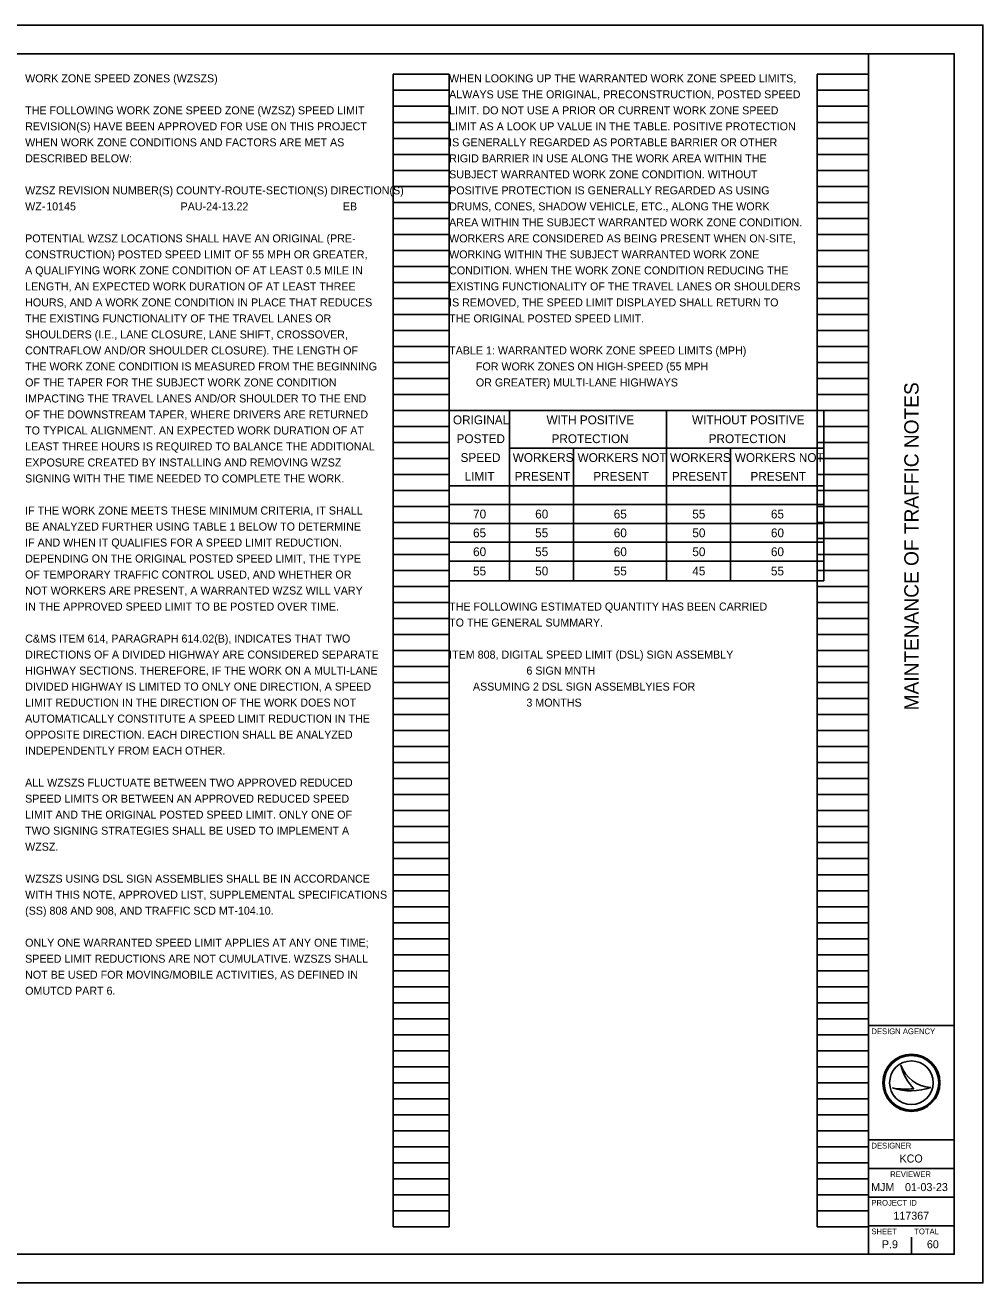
# Model space of a CAD drawing. Extents: x 0 to 34, y 0 to 22.
# Drawn here: x 17.24 to 34, y 0 to 22 of the extents above; entities that cross this region are included whole.
import ezdxf

# ---------------------------------------------------------------- set-up
doc = ezdxf.new("R2010")
doc.units = 0
for name, color, linetype in [('SH_Border', 7, 'Continuous'), ('SH_Cut_Line', 7, 'Continuous'), ('SH_Data', 7, 'Continuous'), ('SH_Text', 7, 'Continuous')]:
    doc.layers.add(name, color=color, linetype=linetype)

msp = doc.modelspace()

# ---------------------------------------------------------------- linework, layer by layer
at = {"layer": 'SH_Border'}
for p, q in [((32, 0.5), (32, 21.5)), ((32, 4.5), (33.5, 4.5)), ((32, 2.5), (33.5, 2.5)), ((32, 2), (33.5, 2)), ((32, 1.5), (33.5, 1.5)), ((32, 1), (33.5, 1))]:
    msp.add_line(p, q, dxfattribs=at)
msp.add_lwpolyline([(1.5, 21.5), (33.5, 21.5), (33.5, 0.5), (1.5, 0.5)], close=True, dxfattribs=at)
at = {"layer": 'SH_Cut_Line'}
msp.add_lwpolyline([(0, 0), (34, 0), (34, 22), (0, 22)], close=True, dxfattribs=at)
at = {"layer": 'SH_Data'}
for p, q in [((23.68, 0.98), (23.68, 21.14)), ((23.68, 21.14), (24.66, 21.14)), ((24.66, 0.98), (24.66, 21.14)), ((31.1, 0.98), (31.1, 21.14)), ((31.1, 21.14), (32, 21.14)), ((32, 0.98), (32, 21.14)), ((23.68, 20.86), (24.66, 20.86)), ((31.1, 20.86), (32, 20.86)), ((23.68, 20.58), (24.66, 20.58)), ((31.1, 20.58), (32, 20.58)), ((23.68, 20.3), (24.66, 20.3)), ((31.1, 20.3), (32, 20.3)), ((23.68, 20.02), (24.66, 20.02)), ((31.1, 20.02), (32, 20.02)), ((23.68, 19.74), (24.66, 19.74)), ((31.1, 19.74), (32, 19.74)), ((23.68, 19.46), (24.66, 19.46)), ((31.1, 19.46), (32, 19.46)), ((23.68, 19.18), (24.66, 19.18)), ((31.1, 19.18), (32, 19.18)), ((23.68, 18.9), (24.66, 18.9)), ((31.1, 18.9), (32, 18.9)), ((23.68, 18.62), (24.66, 18.62)), ((31.1, 18.62), (32, 18.62)), ((23.68, 18.34), (24.66, 18.34)), ((31.1, 18.34), (32, 18.34)), ((23.68, 18.06), (24.66, 18.06)), ((31.1, 18.06), (32, 18.06)), ((23.68, 17.78), (24.66, 17.78)), ((31.1, 17.78), (32, 17.78)), ((23.68, 17.5), (24.66, 17.5)), ((31.1, 17.5), (32, 17.5)), ((23.68, 17.22), (24.66, 17.22)), ((31.1, 17.22), (32, 17.22)), ((23.68, 16.94), (24.66, 16.94)), ((31.1, 16.94), (32, 16.94)), ((23.68, 16.66), (24.66, 16.66)), ((31.1, 16.66), (32, 16.66)), ((23.68, 16.38), (24.66, 16.38)), ((31.1, 16.38), (32, 16.38)), ((23.68, 16.1), (24.66, 16.1)), ((31.1, 16.1), (32, 16.1)), ((23.68, 15.82), (24.66, 15.82)), ((31.1, 15.82), (32, 15.82)), ((23.68, 15.54), (24.66, 15.54)), ((31.1, 15.54), (32, 15.54)), ((23.68, 15.26), (24.66, 15.26)), ((31.1, 15.26), (32, 15.26)), ((23.68, 14.98), (24.66, 14.98)), ((31.1, 14.98), (32, 14.98)), ((23.68, 14.7), (24.66, 14.7)), ((31.1, 14.7), (32, 14.7)), ((23.68, 14.42), (24.66, 14.42)), ((31.1, 14.42), (32, 14.42)), ((23.68, 14.14), (24.66, 14.14)), ((31.1, 14.14), (32, 14.14)), ((23.68, 13.86), (24.66, 13.86)), ((31.1, 13.86), (32, 13.86)), ((23.68, 13.58), (24.66, 13.58)), ((31.1, 13.58), (32, 13.58)), ((23.68, 13.3), (24.66, 13.3)), ((31.1, 13.3), (32, 13.3)), ((23.68, 13.02), (24.66, 13.02)), ((31.1, 13.02), (32, 13.02)), ((23.68, 12.74), (24.66, 12.74)), ((31.1, 12.74), (32, 12.74)), ((23.68, 12.46), (24.66, 12.46)), ((31.1, 12.46), (32, 12.46)), ((23.68, 12.18), (24.66, 12.18)), ((31.1, 12.18), (32, 12.18)), ((23.68, 11.9), (24.66, 11.9)), ((31.1, 11.9), (32, 11.9)), ((23.68, 11.62), (24.66, 11.62)), ((31.1, 11.62), (32, 11.62)), ((23.68, 11.34), (24.66, 11.34)), ((31.1, 11.34), (32, 11.34)), ((23.68, 11.06), (24.66, 11.06)), ((31.1, 11.06), (32, 11.06)), ((23.68, 10.78), (24.66, 10.78)), ((31.1, 10.78), (32, 10.78)), ((23.68, 10.5), (24.66, 10.5)), ((31.1, 10.5), (32, 10.5)), ((23.68, 10.22), (24.66, 10.22)), ((31.1, 10.22), (32, 10.22)), ((23.68, 9.94), (24.66, 9.94)), ((31.1, 9.94), (32, 9.94)), ((23.68, 9.66), (24.66, 9.66)), ((31.1, 9.66), (32, 9.66)), ((23.68, 9.38), (24.66, 9.38)), ((31.1, 9.38), (32, 9.38)), ((23.68, 9.1), (24.66, 9.1)), ((31.1, 9.1), (32, 9.1)), ((23.68, 8.82), (24.66, 8.82)), ((31.1, 8.82), (32, 8.82)), ((23.68, 8.54), (24.66, 8.54)), ((31.1, 8.54), (32, 8.54)), ((23.68, 8.26), (24.66, 8.26)), ((31.1, 8.26), (32, 8.26)), ((23.68, 7.98), (24.66, 7.98)), ((31.1, 7.98), (32, 7.98)), ((23.68, 7.7), (24.66, 7.7)), ((31.1, 7.7), (32, 7.7)), ((23.68, 7.42), (24.66, 7.42)), ((31.1, 7.42), (32, 7.42)), ((23.68, 7.14), (24.66, 7.14)), ((31.1, 7.14), (32, 7.14)), ((23.68, 6.86), (24.66, 6.86)), ((31.1, 6.86), (32, 6.86)), ((23.68, 6.58), (24.66, 6.58)), ((31.1, 6.58), (32, 6.58)), ((23.68, 6.3), (24.66, 6.3)), ((31.1, 6.3), (32, 6.3)), ((23.68, 6.02), (24.66, 6.02)), ((31.1, 6.02), (32, 6.02)), ((23.68, 5.74), (24.66, 5.74)), ((31.1, 5.74), (32, 5.74)), ((23.68, 5.46), (24.66, 5.46)), ((31.1, 5.46), (32, 5.46)), ((23.68, 5.18), (24.66, 5.18)), ((31.1, 5.18), (32, 5.18)), ((23.68, 4.9), (24.66, 4.9)), ((31.1, 4.9), (32, 4.9)), ((23.68, 4.62), (24.66, 4.62)), ((31.1, 4.62), (32, 4.62)), ((23.68, 4.34), (24.66, 4.34)), ((31.1, 4.34), (32, 4.34)), ((23.68, 4.06), (24.66, 4.06)), ((31.1, 4.06), (32, 4.06)), ((23.68, 3.78), (24.66, 3.78)), ((31.1, 3.78), (32, 3.78)), ((32.567, 3.81), (32.567, 3.81)), ((23.68, 3.5), (24.66, 3.5)), ((31.1, 3.5), (32, 3.5)), ((32.417, 3.41), (32.417, 3.41)), ((32.75, 3.5), (32.75, 3.5)), ((33.087, 3.419), (33.087, 3.419)), ((23.68, 3.22), (24.66, 3.22)), ((31.1, 3.22), (32, 3.22)), ((23.68, 2.94), (24.66, 2.94)), ((31.1, 2.94), (32, 2.94)), ((23.68, 2.66), (24.66, 2.66)), ((31.1, 2.66), (32, 2.66)), ((23.68, 2.38), (24.66, 2.38)), ((31.1, 2.38), (32, 2.38)), ((23.68, 2.1), (24.66, 2.1)), ((31.1, 2.1), (32, 2.1)), ((23.68, 1.82), (24.66, 1.82)), ((31.1, 1.82), (32, 1.82)), ((23.68, 1.54), (24.66, 1.54)), ((31.1, 1.54), (32, 1.54)), ((23.68, 1.26), (24.66, 1.26)), ((31.1, 1.26), (32, 1.26)), ((23.68, 0.98), (24.66, 0.98)), ((31.1, 0.98), (32, 0.98)), ((32.375, 0.675), (32.375, 0.675)), ((32.75, 0.5), (32.75, 0.8))]:
    msp.add_line(p, q, dxfattribs=at)
for radius in [0.5, 0.477, 0.477, 0.382]:
    msp.add_circle((32.75, 3.5), radius, dxfattribs=at)
for centre, radius, start, end in [((33.116, 3.998), 0.58, 198.9257, 198.9319), ((33.347, 3.97), 0.796, 191.6379, 191.6421), ((33.116, 3.998), 0.58, 198.9319, 267.1657), ((33.347, 3.97), 0.796, 191.6421, 226.0947), ((32.739, 4.37), 1.013, 251.4576, 290.0832), ((32.648, 4.654), 1.266, 259.4964, 259.4995), ((32.739, 4.37), 1.013, 251.4527, 251.4576), ((32.648, 4.654), 1.266, 259.4995, 276.6672)]:
    msp.add_arc(centre, radius, start, end, dxfattribs=at)
at = {"layer": 'SH_Text'}
for p, q in [((24.66, 15.26), (31.215, 15.26)), ((24.66, 15.26), (24.66, 12.279)), ((25.714, 15.26), (25.714, 12.279)), ((28.465, 15.26), (28.465, 12.279)), ((31.215, 15.26), (31.215, 12.279)), ((25.714, 14.601), (31.215, 14.601)), ((26.834, 14.601), (26.834, 12.279)), ((29.585, 14.601), (29.585, 12.279)), ((24.66, 13.942), (31.215, 13.942)), ((24.66, 13.613), (31.215, 13.613)), ((24.66, 13.284), (31.215, 13.284)), ((24.66, 12.954), (31.215, 12.954)), ((24.66, 12.625), (31.215, 12.625)), ((24.66, 12.279), (31.215, 12.279))]:
    msp.add_line(p, q, dxfattribs=at)

# ---------------------------------------------------------------- texts
at = {"layer": 'SH_Data'}
msp.add_text('MAINTENANCE OF TRAFFIC NOTES', height=0.25, rotation=90, dxfattribs=at).set_placement((32.875, 10.014))
for s, height, p in [('DESIGN AGENCY', 0.1, (32.05, 4.35)), ('DESIGNER', 0.1, (32.05, 2.35)), ('KCO', 0.14, (32.542, 2.105)), ('REVIEWER', 0.1, (32.378, 1.85)), ('MJM', 0.14, (32.045, 1.605)), ('01-03-23', 0.14, (32.638, 1.605)), ('PROJECT ID', 0.1, (32.05, 1.35)), ('117367', 0.14, (32.435, 1.105)), ('SHEET', 0.1, (32.05, 0.85)), ('TOTAL', 0.1, (32.8, 0.85)), ('P.9', 0.14, (32.233, 0.605)), ('60', 0.14, (33.021, 0.605))]:
    msp.add_text(s, height=height, dxfattribs=at).set_placement(p)
at = {"layer": 'SH_Text'}
for s, height, p in [('WORK ZONE SPEED ZONES (WZSZS)', 0.14, (17.24, 21)), ('WHEN LOOKING UP THE WARRANTED WORK ZONE SPEED LIMITS,', 0.14, (24.66, 21)), ('ALWAYS USE THE ORIGINAL, PRECONSTRUCTION, POSTED SPEED', 0.14, (24.66, 20.72)), ('THE FOLLOWING WORK ZONE SPEED ZONE (WZSZ) SPEED LIMIT', 0.14, (17.24, 20.44)), ('LIMIT. DO NOT USE A PRIOR OR CURRENT WORK ZONE SPEED', 0.14, (24.66, 20.44)), ('REVISION(S) HAVE BEEN APPROVED FOR USE ON THIS PROJECT', 0.14, (17.24, 20.16)), ('LIMIT AS A LOOK UP VALUE IN THE TABLE. POSITIVE PROTECTION', 0.14, (24.66, 20.16)), ('WHEN WORK ZONE CONDITIONS AND FACTORS ARE MET AS', 0.14, (17.24, 19.88)), ('IS GENERALLY REGARDED AS PORTABLE BARRIER OR OTHER', 0.14, (24.66, 19.88)), ('DESCRIBED BELOW:', 0.14, (17.24, 19.6)), ('RIGID BARRIER IN USE ALONG THE WORK AREA WITHIN THE', 0.14, (24.66, 19.6)), ('SUBJECT WARRANTED WORK ZONE CONDITION. WITHOUT', 0.14, (24.66, 19.32)), ('WZSZ REVISION NUMBER(S) COUNTY-ROUTE-SECTION(S) DIRECTION(S)', 0.14, (17.24, 19.04)), ('POSITIVE PROTECTION IS GENERALLY REGARDED AS USING', 0.14, (24.66, 19.04)), ('WZ-', 0.14, (17.24, 18.76)), ('10145', 0.14, (17.609, 18.76)), ('                    PAU-24-13.22', 0.14, (18.92, 18.76)), ('          EB', 0.14, (22.28, 18.76)), ('DRUMS, CONES, SHADOW VEHICLE, ETC., ALONG THE WORK', 0.14, (24.66, 18.76)), ('AREA WITHIN THE SUBJECT WARRANTED WORK ZONE CONDITION.', 0.14, (24.66, 18.48)), ('POTENTIAL WZSZ LOCATIONS SHALL HAVE AN ORIGINAL (PRE-', 0.14, (17.24, 18.2)), ('WORKERS ARE CONSIDERED AS BEING PRESENT WHEN ON-SITE,', 0.14, (24.66, 18.2)), ('CONSTRUCTION) POSTED SPEED LIMIT OF 55 MPH OR GREATER,', 0.14, (17.24, 17.92)), ('WORKING WITHIN THE SUBJECT WARRANTED WORK ZONE', 0.14, (24.66, 17.92)), ('A QUALIFYING WORK ZONE CONDITION OF AT LEAST 0.5 MILE IN', 0.14, (17.24, 17.64)), ('CONDITION. WHEN THE WORK ZONE CONDITION REDUCING THE', 0.14, (24.66, 17.64)), ('LENGTH, AN EXPECTED WORK DURATION OF AT LEAST THREE', 0.14, (17.24, 17.36)), ('EXISTING FUNCTIONALITY OF THE TRAVEL LANES OR SHOULDERS', 0.14, (24.66, 17.36)), ('HOURS, AND A WORK ZONE CONDITION IN PLACE THAT REDUCES', 0.14, (17.24, 17.08)), ('IS REMOVED, THE SPEED LIMIT DISPLAYED SHALL RETURN TO', 0.14, (24.66, 17.08)), ('THE EXISTING FUNCTIONALITY OF THE TRAVEL LANES OR', 0.14, (17.24, 16.8)), ('THE ORIGINAL POSTED SPEED LIMIT.', 0.14, (24.66, 16.8)), ('SHOULDERS (I.E., LANE CLOSURE, LANE SHIFT, CROSSOVER,', 0.14, (17.24, 16.52)), ('CONTRAFLOW AND/OR SHOULDER CLOSURE). THE LENGTH OF', 0.14, (17.24, 16.24)), ('TABLE 1: WARRANTED WORK ZONE SPEED LIMITS (MPH)', 0.14, (24.66, 16.24)), ('THE WORK ZONE CONDITION IS MEASURED FROM THE BEGINNING', 0.14, (17.24, 15.96)), ('         FOR WORK ZONES ON HIGH-SPEED (55 MPH', 0.14, (24.66, 15.96)), ('OF THE TAPER FOR THE SUBJECT WORK ZONE CONDITION', 0.14, (17.24, 15.68)), ('         OR GREATER) MULTI-LANE HIGHWAYS', 0.14, (24.66, 15.68)), ('IMPACTING THE TRAVEL LANES AND/OR SHOULDER TO THE END', 0.14, (17.24, 15.4)), ('OF THE DOWNSTREAM TAPER, WHERE DRIVERS ARE RETURNED', 0.14, (17.24, 15.12)), ('TO TYPICAL ALIGNMENT. AN EXPECTED WORK DURATION OF AT', 0.14, (17.24, 14.84)), ('ORIGINAL', 0.154, (24.727, 15.018)), ('WITH POSITIVE', 0.154, (26.364, 15.018)), ('WITHOUT POSITIVE', 0.154, (28.91, 15.018)), ('POSTED', 0.154, (24.79, 14.689)), ('PROTECTION', 0.154, (26.452, 14.689)), ('PROTECTION', 0.154, (29.202, 14.689)), ('LEAST THREE HOURS IS REQUIRED TO BALANCE THE ADDITIONAL', 0.14, (17.24, 14.56)), ('EXPOSURE CREATED BY INSTALLING AND REMOVING WZSZ', 0.14, (17.24, 14.28)), ('SPEED', 0.154, (24.86, 14.359)), ('WORKERS', 0.154, (25.773, 14.359)), ('WORKERS NOT', 0.154, (26.908, 14.359)), ('WORKERS', 0.154, (28.524, 14.359)), ('WORKERS NOT', 0.154, (29.659, 14.359)), ('SIGNING WITH THE TIME NEEDED TO COMPLETE THE WORK.', 0.14, (17.24, 14)), ('LIMIT', 0.154, (24.93, 14.03)), ('PRESENT', 0.154, (25.807, 14.03)), ('PRESENT', 0.154, (27.182, 14.03)), ('PRESENT', 0.154, (28.558, 14.03)), ('PRESENT', 0.154, (29.933, 14.03)), ('IF THE WORK ZONE MEETS THESE MINIMUM CRITERIA, IT SHALL', 0.14, (17.24, 13.44)), ('70', 0.154, (25.079, 13.371)), ('60', 0.154, (26.166, 13.371)), ('65', 0.154, (27.54, 13.371)), ('55', 0.154, (28.915, 13.371)), ('65', 0.154, (30.291, 13.371)), ('BE ANALYZED FURTHER USING TABLE 1 BELOW TO DETERMINE', 0.14, (17.24, 13.16)), ('IF AND WHEN IT QUALIFIES FOR A SPEED LIMIT REDUCTION.', 0.14, (17.24, 12.88)), ('65', 0.154, (25.078, 13.042)), ('55', 0.154, (26.165, 13.042)), ('60', 0.154, (27.541, 13.042)), ('50', 0.154, (28.916, 13.042)), ('60', 0.154, (30.291, 13.042)), ('60', 0.154, (25.079, 12.712)), ('55', 0.154, (26.165, 12.712)), ('60', 0.154, (27.541, 12.712)), ('50', 0.154, (28.916, 12.712)), ('60', 0.154, (30.291, 12.712)), ('DEPENDING ON THE ORIGINAL POSTED SPEED LIMIT, THE TYPE', 0.14, (17.24, 12.6)), ('OF TEMPORARY TRAFFIC CONTROL USED, AND WHETHER OR', 0.14, (17.24, 12.32)), ('55', 0.154, (25.078, 12.375)), ('50', 0.154, (26.166, 12.375)), ('55', 0.154, (27.54, 12.375)), ('45', 0.154, (28.915, 12.375)), ('55', 0.154, (30.291, 12.375)), ('NOT WORKERS ARE PRESENT, A WARRANTED WZSZ WILL VARY', 0.14, (17.24, 12.04)), ('IN THE APPROVED SPEED LIMIT TO BE POSTED OVER TIME.', 0.14, (17.24, 11.76)), ('THE FOLLOWING ESTIMATED QUANTITY HAS BEEN CARRIED', 0.14, (24.66, 11.76)), ('TO THE GENERAL SUMMARY.', 0.14, (24.66, 11.48)), ('C&MS ITEM 614, PARAGRAPH 614.02(B), INDICATES THAT TWO', 0.14, (17.24, 11.2)), ('DIRECTIONS OF A DIVIDED HIGHWAY ARE CONSIDERED SEPARATE', 0.14, (17.24, 10.92)), ('ITEM 808, DIGITAL SPEED LIMIT (DSL) SIGN ASSEMBLY', 0.14, (24.66, 10.92)), ('HIGHWAY SECTIONS. THEREFORE, IF THE WORK ON A MULTI-LANE', 0.14, (17.24, 10.64)), ('                          6 SIGN MNTH', 0.14, (24.66, 10.64)), ('DIVIDED HIGHWAY IS LIMITED TO ONLY ONE DIRECTION, A SPEED', 0.14, (17.24, 10.36)), ('        ASSUMING 2 DSL SIGN ASSEMBLYIES FOR', 0.14, (24.66, 10.36)), ('LIMIT REDUCTION IN THE DIRECTION OF THE WORK DOES NOT', 0.14, (17.24, 10.08)), ('                          3 MONTHS', 0.14, (24.66, 10.08)), ('AUTOMATICALLY CONSTITUTE A SPEED LIMIT REDUCTION IN THE', 0.14, (17.24, 9.8)), ('OPPOSITE DIRECTION. EACH DIRECTION SHALL BE ANALYZED', 0.14, (17.24, 9.52)), ('INDEPENDENTLY FROM EACH OTHER.', 0.14, (17.24, 9.24)), ('ALL WZSZS FLUCTUATE BETWEEN TWO APPROVED REDUCED', 0.14, (17.24, 8.68)), ('SPEED LIMITS OR BETWEEN AN APPROVED REDUCED SPEED', 0.14, (17.24, 8.4)), ('LIMIT AND THE ORIGINAL POSTED SPEED LIMIT. ONLY ONE OF', 0.14, (17.24, 8.12)), ('TWO SIGNING STRATEGIES SHALL BE USED TO IMPLEMENT A', 0.14, (17.24, 7.84)), ('WZSZ.', 0.14, (17.24, 7.56)), ('WZSZS USING DSL SIGN ASSEMBLIES SHALL BE IN ACCORDANCE', 0.14, (17.24, 7)), ('WITH THIS NOTE, APPROVED LIST, SUPPLEMENTAL SPECIFICATIONS', 0.14, (17.24, 6.72)), ('(SS) 808 AND 908, AND TRAFFIC SCD MT-104.10.', 0.14, (17.24, 6.44)), ('ONLY ONE WARRANTED SPEED LIMIT APPLIES AT ANY ONE TIME;', 0.14, (17.24, 5.88)), ('SPEED LIMIT REDUCTIONS ARE NOT CUMULATIVE. WZSZS SHALL', 0.14, (17.24, 5.6)), ('NOT BE USED FOR MOVING/MOBILE ACTIVITIES, AS DEFINED IN', 0.14, (17.24, 5.32)), ('OMUTCD PART 6.', 0.14, (17.24, 5.04))]:
    msp.add_text(s, height=height, dxfattribs=at).set_placement(p)

doc.saveas('drawing.dxf')
